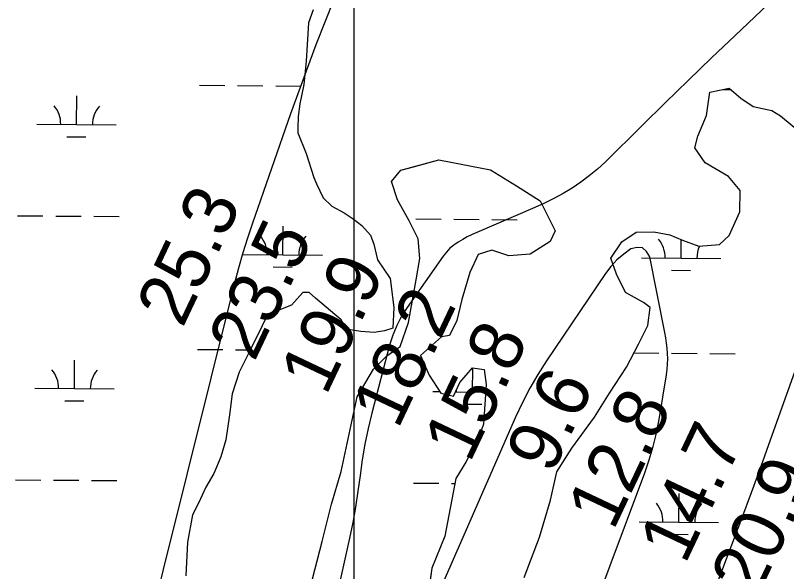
# Model space of a CAD drawing. Extents: x 3271442 to 3309282, y 752266 to 777610.
# Drawn here: x 3285650 to 3286622, y 765409 to 766109 of the extents above; entities that cross this region are included whole.
import ezdxf

# ---------------------------------------------------------------- set-up
doc = ezdxf.new("R2010")
doc.units = 0
for name, color, linetype in [('V-GRID-MAJR', 7, 'Continuous'), ('V-RIVR-RANG', 7, 'Continuous'), ('V-SITE-VEGE', 7, 'Continuous'), ('V-TOPO-DPTH', 7, 'Continuous'), ('V-TOPO-MINR', 7, 'Continuous'), ('V-TOPO-SHOR', 7, 'Continuous'), ('V-WETL-SWMP', 7, 'Continuous')]:
    doc.layers.add(name, color=color, linetype=linetype)

msp = doc.modelspace()

# ---------------------------------------------------------------- linework, layer by layer
at = {"layer": 'V-GRID-MAJR'}
msp.add_spline([(3286078.01, 757644.71), (3286077.13, 763703.55), (3286076.24, 769765.48), (3286075.36, 775827.44), (3286075.36, 775830.49)], degree=3, dxfattribs=at)
at = {"layer": 'V-SITE-VEGE'}
for p, q in [((3286025.27, 766116.4), (3286019.52, 766099.95)), ((3286019.52, 766099.95), (3286016.48, 766051.66)), ((3286016.48, 766051.66), (3286013.52, 766022.12)), ((3286013.52, 766022.12), (3286008.31, 765997.7)), ((3286521.18, 765982.96), (3286525.36, 766012.34)), ((3286525.36, 766012.34), (3286549.63, 766017.37)), ((3286549.63, 766017.37), (3286564.64, 766005.18)), ((3286564.64, 766005.18), (3286580.03, 765994.46)), ((3286008.31, 765997.7), (3286006.54, 765981.8)), ((3286580.03, 765994.46), (3286603.52, 765989.58)), ((3286006.54, 765981.8), (3286005.91, 765967.59)), ((3286510.41, 765956.92), (3286521.18, 765982.96)), ((3286603.52, 765989.58), (3286614.51, 765982.54)), ((3286614.51, 765982.54), (3286643.8, 765958.53)), ((3286005.91, 765967.59), (3286005.89, 765961.34)), ((3286005.89, 765961.34), (3286016.58, 765935.15)), ((3286506.31, 765942.24), (3286510.41, 765956.92)), ((3286519.45, 765923.44), (3286506.31, 765942.24)), ((3286016.58, 765935.15), (3286026.11, 765905)), ((3286135.79, 765914.12), (3286183.62, 765927.14)), ((3286183.62, 765927.14), (3286211.89, 765921.87)), ((3286548.77, 765906.41), (3286519.45, 765923.44)), ((3286123.97, 765899.84), (3286135.79, 765914.12)), ((3286211.89, 765921.87), (3286248.97, 765914.72)), ((3286248.97, 765914.72), (3286281.58, 765894.73)), ((3286026.11, 765905), (3286029.49, 765897.03)), ((3286563.76, 765888.7), (3286548.77, 765906.41)), ((3286029.49, 765897.03), (3286037.94, 765879.37)), ((3286131.58, 765877.03), (3286123.97, 765899.84)), ((3286281.58, 765894.73), (3286311.63, 765875.49)), ((3286563.27, 765861.88), (3286563.76, 765888.7)), ((3286037.94, 765879.37), (3286048.7, 765869.1)), ((3286146.53, 765850.51), (3286131.58, 765877.03)), ((3286311.63, 765875.49), (3286330.2, 765837.93)), ((3286048.7, 765869.1), (3286064.58, 765860.51)), ((3286064.58, 765860.51), (3286075.91, 765853.08)), ((3286549.54, 765831.81), (3286563.27, 765861.88)), ((3286075.91, 765853.08), (3286086.68, 765844.51)), ((3286086.68, 765844.51), (3286097.43, 765832.53)), ((3286157.46, 765827.68), (3286146.53, 765850.51)), ((3286330.2, 765837.93), (3286324.26, 765824.36)), ((3286414.29, 765823.96), (3286432.35, 765836.37)), ((3286432.35, 765836.37), (3286454.76, 765836.64)), ((3286454.76, 765836.64), (3286474.95, 765832.88)), ((3286097.43, 765832.53), (3286101.93, 765821.15)), ((3286159.92, 765803.05), (3286157.46, 765827.68)), ((3286474.95, 765832.88), (3286490.72, 765826.19)), ((3286490.72, 765826.19), (3286511.63, 765818.39)), ((3286537.36, 765820.47), (3286549.54, 765831.81)), ((3286101.93, 765821.15), (3286106.39, 765801.24)), ((3286324.26, 765824.36), (3286298.84, 765808.68)), ((3286400.6, 765803.44), (3286414.29, 765823.96)), ((3286511.63, 765818.39), (3286537.36, 765820.47)), ((3286233.43, 765808.23), (3286222.68, 765785.5)), ((3286250.36, 765813.67), (3286233.43, 765808.23)), ((3286272, 765806.22), (3286250.36, 765813.67)), ((3286298.84, 765808.68), (3286272, 765806.22)), ((3286106.39, 765801.24), (3286122.21, 765777.87)), ((3286155.02, 765776.25), (3286159.92, 765803.05)), ((3286407.49, 765783.2), (3286400.6, 765803.44)), ((3286122.21, 765777.87), (3286127.17, 765741.48)), ((3286145.6, 765722.27), (3286155.02, 765776.25)), ((3286222.68, 765785.5), (3286212.6, 765751.37)), ((3286419.15, 765760.37), (3286407.49, 765783.2)), ((3286012.45, 765760.13), (3285998.18, 765744.28)), ((3286020.41, 765760.1), (3286012.45, 765760.13)), ((3286028.34, 765753.25), (3286020.41, 765760.1)), ((3286441.87, 765747.41), (3286419.15, 765760.37)), ((3286060.62, 765725.84), (3286028.34, 765753.25)), ((3286212.6, 765751.37), (3286206.24, 765724.94)), ((3286450.29, 765741.13), (3286441.87, 765747.41)), ((3285983.95, 765738.66), (3285967.44, 765731.33)), ((3285998.18, 765744.28), (3285983.95, 765738.66)), ((3286127.17, 765741.48), (3286125.93, 765715.34)), ((3286447.25, 765718.73), (3286450.29, 765741.13)), ((3285967.44, 765731.33), (3285961.14, 765718.29)), ((3285961.14, 765718.29), (3285946.24, 765688.23)), ((3286066.82, 765713.88), (3286060.62, 765725.84)), ((3286134.81, 765692.19), (3286145.6, 765722.27)), ((3286206.24, 765724.94), (3286197.33, 765705.87)), ((3286435.39, 765695.26), (3286447.25, 765718.73)), ((3286085.56, 765710.96), (3286066.82, 765713.88)), ((3286102.04, 765709.76), (3286085.56, 765710.96)), ((3286115.12, 765711.98), (3286102.04, 765709.76)), ((3286125.93, 765715.34), (3286115.12, 765711.98)), ((3286187.04, 765704.45), (3286160.48, 765680.68)), ((3286197.33, 765705.87), (3286187.04, 765704.45)), ((3286118.22, 765680.5), (3286134.81, 765692.19)), ((3286420.2, 765666.3), (3286435.39, 765695.26)), ((3285946.24, 765688.23), (3285931.91, 765659.88)), ((3286101.24, 765663.68), (3286118.22, 765680.5)), ((3286160.48, 765680.68), (3286171.39, 765656.02)), ((3285931.91, 765659.88), (3285923.28, 765632.63)), ((3286080.88, 765628.86), (3286101.24, 765663.68)), ((3286210.3, 765647.02), (3286226.18, 765665.33)), ((3286226.18, 765665.33), (3286240.87, 765663.06)), ((3286240.87, 765663.06), (3286243.36, 765644.31)), ((3286398.74, 765633.33), (3286420.2, 765666.3)), ((3286171.39, 765656.02), (3286186.36, 765633.53)), ((3286202.14, 765629.79), (3286210.3, 765647.02)), ((3286243.36, 765644.31), (3286240.2, 765594.35)), ((3285923.28, 765632.63), (3285919.76, 765605.93)), ((3286186.36, 765633.53), (3286202.14, 765629.79)), ((3286379.87, 765603.28), (3286398.74, 765633.33)), ((3286060.62, 765534.52), (3286080.88, 765628.86)), ((3285919.76, 765605.93), (3285915.09, 765574.7)), ((3286351.4, 765564.09), (3286379.87, 765603.28)), ((3286240.2, 765594.35), (3286233.13, 765575.27)), ((3285915.09, 765574.7), (3285908.75, 765553.13)), ((3286233.13, 765575.27), (3286217.57, 765546.68)), ((3286332.53, 765534.41), (3286351.4, 765564.09)), ((3285908.75, 765553.13), (3285900.14, 765532.14)), ((3286217.57, 765546.68), (3286205.35, 765525.79)), ((3286048.31, 765493.78), (3286060.62, 765534.52)), ((3286324.65, 765498.8), (3286332.53, 765534.41)), ((3285900.14, 765532.14), (3285889.84, 765515.13)), ((3286205.35, 765525.79), (3286191.43, 765453.1)), ((3285889.84, 765515.13), (3285880.66, 765494.7)), ((3285880.66, 765494.7), (3285873.21, 765479.96)), ((3286310.48, 765452.2), (3286324.65, 765498.8)), ((3286036.71, 765446.43), (3286048.31, 765493.78)), ((3285873.21, 765479.96), (3285866.82, 765445.89)), ((3285866.82, 765445.89), (3285864.95, 765403.27)), ((3286021.01, 765386.61), (3286036.71, 765446.43)), ((3286191.43, 765453.1), (3286174.72, 765413.12)), ((3286291.15, 765401.21), (3286310.48, 765452.2)), ((3286174.72, 765413.12), (3286169.03, 765372.36))]:
    msp.add_line(p, q, dxfattribs=at)
at = {"layer": 'V-TOPO-DPTH'}
msp.add_lwpolyline([(3286141.36, 764725.96), (3286443.39, 765533.11), (3286449.01, 765549.59), (3286453.99, 765566.24), (3286457.98, 765583.16), (3286461.33, 765600.25), (3286470.68, 765656.69), (3286471.54, 765663.31), (3286472.1, 765669.94), (3286472.21, 765676.6), (3286472, 765683.27), (3286471.44, 765689.93), (3286470.71, 765696.57), (3286469.71, 765703.18), (3286468.54, 765709.77), (3286449.71, 765805.02), (3286445.65, 765811.95), (3286440.52, 765816.38), (3286433.77, 765817.06), (3286425.95, 765815.23), (3286416.78, 765808.6), (3286408.27, 765801.31), (3286400.72, 765793.02), (3286393.81, 765784.06), (3286319.52, 765674.17), (3286308.62, 765657.07), (3286298.37, 765639.61), (3286289.09, 765621.61), (3286280.46, 765603.26), (3286092.7, 765174.28)], dxfattribs=at)
at = {"layer": 'V-TOPO-MINR'}
for points in [[(3286062.67, 766158.12), (3286028.87, 766072), (3285996.92, 765985.12), (3285948.83, 765847.51), (3285942.58, 765828.78), (3285936.67, 765809.95), (3285931.28, 765790.97), (3285926.23, 765771.88), (3285836.27, 765411.46), (3285825.32, 765365.74), (3285814.97, 765319.89), (3285805.49, 765273.85), (3285796.61, 765227.69), (3285789.16, 765181.32), (3285783.03, 765134.8), (3285778.87, 765088.07), (3285776.04, 765041.19), (3285769.47, 764873.26), (3285713.83, 764763.83), (3285687.23, 764708.6), (3285683.59, 764700.44)], [(3286598.28, 766122.93), (3286557.12, 766083.91), (3286527.66, 766055.81), (3286498.31, 766027.6), (3286469.13, 765999.2), (3286440.06, 765970.7), (3286393.29, 765924.55), (3286383.55, 765915.56), (3286373.45, 765907.02), (3286362.8, 765899.17), (3286351.8, 765891.78), (3286340.37, 765885.01), (3286328.76, 765878.6), (3286316.87, 765872.73), (3286304.79, 765867.22), (3286231.63, 765835.87), (3286225.59, 765833.13), (3286219.64, 765830.22), (3286213.81, 765827.07), (3286208.07, 765823.75), (3286202.68, 765820), (3286197.66, 765815.85), (3286193.18, 765811.12), (3286189.08, 765805.99), (3286143.74, 765741.43), (3286136.74, 765730.23), (3286130.59, 765718.64), (3286125.7, 765706.45), (3286121.65, 765693.88), (3286099.13, 765608.38), (3286094.44, 765588.9), (3286090.33, 765569.31), (3286087.07, 765549.56), (3286084.37, 765529.7), (3286081.79, 765509.81), (3286078.79, 765490), (3286075.16, 765470.29), (3286071.1, 765450.66), (3286038.19, 765303.19)], [(3286141.36, 764725.96), (3286443.39, 765533.11), (3286449.01, 765549.59), (3286453.99, 765566.24), (3286457.98, 765583.16), (3286461.33, 765600.25), (3286470.68, 765656.69), (3286471.54, 765663.31), (3286472.1, 765669.94), (3286472.21, 765676.6), (3286472, 765683.27), (3286471.44, 765689.93), (3286470.71, 765696.57), (3286469.71, 765703.18), (3286468.54, 765709.77), (3286449.71, 765805.02), (3286445.65, 765811.95), (3286440.52, 765816.38), (3286433.77, 765817.06), (3286425.95, 765815.23), (3286416.78, 765808.6), (3286408.27, 765801.31), (3286400.72, 765793.02), (3286393.81, 765784.06), (3286319.52, 765674.17), (3286308.62, 765657.07), (3286298.37, 765639.61), (3286289.09, 765621.61), (3286280.46, 765603.26), (3286092.7, 765174.28)], [(3286182.77, 764319.84), (3286261.5, 764619.04), (3286268.87, 764645.82), (3286276.62, 764672.49), (3286284.96, 764698.97), (3286293.69, 764725.34), (3286347.74, 764882.72), (3286384.31, 764987.5), (3286421.57, 765092.03), (3286459.89, 765196.18), (3286498.9, 765300.08), (3286553.15, 765442.39), (3286565.59, 765475.32), (3286577.88, 765508.29), (3286589.97, 765541.34), (3286601.93, 765574.44), (3286684.27, 765804.68)]]:
    msp.add_lwpolyline(points, dxfattribs=at)
at = {"layer": 'V-TOPO-SHOR'}
for points in [[(3286025.27, 766116.41), (3286019.52, 766099.95), (3286016.48, 766051.66), (3286013.52, 766022.12), (3286008.31, 765997.7), (3286006.54, 765981.8), (3286005.91, 765967.59), (3286005.89, 765961.34), (3286016.58, 765935.15), (3286026.11, 765905), (3286029.49, 765897.03), (3286037.94, 765879.37), (3286048.7, 765869.1), (3286064.58, 765860.51), (3286075.91, 765853.08), (3286086.68, 765844.51), (3286097.43, 765832.53), (3286101.93, 765821.15), (3286106.39, 765801.24), (3286122.21, 765777.87), (3286127.17, 765741.48), (3286125.93, 765715.34), (3286115.12, 765711.98), (3286102.04, 765709.76), (3286085.56, 765710.96), (3286066.82, 765713.88), (3286060.62, 765725.84), (3286028.34, 765753.25), (3286020.41, 765760.1), (3286012.45, 765760.13), (3285998.18, 765744.28), (3285983.95, 765738.66), (3285967.44, 765731.33), (3285961.14, 765718.29), (3285946.24, 765688.23), (3285931.91, 765659.88), (3285923.28, 765632.63), (3285919.76, 765605.93), (3285915.09, 765574.7), (3285908.75, 765553.13), (3285900.14, 765532.14), (3285889.84, 765515.13), (3285880.66, 765494.71), (3285873.21, 765479.96), (3285866.82, 765445.89), (3285864.95, 765403.27)], [(3286435.39, 765695.26), (3286447.25, 765718.73), (3286450.29, 765741.13), (3286441.87, 765747.41), (3286419.15, 765760.37), (3286407.49, 765783.2), (3286400.6, 765803.44), (3286414.29, 765823.96), (3286432.35, 765836.37), (3286454.76, 765836.64), (3286474.95, 765832.88), (3286490.72, 765826.19), (3286511.63, 765818.39), (3286537.36, 765820.47), (3286549.54, 765831.81), (3286563.27, 765861.88), (3286563.76, 765888.7), (3286548.77, 765906.41), (3286519.45, 765923.44), (3286506.31, 765942.24), (3286510.41, 765956.92), (3286521.18, 765982.96), (3286525.36, 766012.34), (3286549.63, 766017.37), (3286564.64, 766005.18), (3286580.03, 765994.46), (3286603.52, 765989.58), (3286614.51, 765982.54), (3286643.8, 765958.53)], [(3286021.01, 765386.61), (3286036.71, 765446.43), (3286048.31, 765493.78), (3286060.62, 765534.52), (3286080.88, 765628.86), (3286101.24, 765663.68), (3286118.22, 765680.5), (3286134.81, 765692.19), (3286145.6, 765722.27), (3286150.12, 765747.97), (3286155.02, 765776.25), (3286159.92, 765803.05), (3286157.46, 765827.68), (3286146.53, 765850.51), (3286131.59, 765877.03), (3286123.97, 765899.84), (3286135.79, 765914.12), (3286151.61, 765918.46), (3286183.62, 765927.14), (3286211.89, 765921.87), (3286248.97, 765914.72), (3286281.58, 765894.73), (3286311.63, 765875.49), (3286330.2, 765837.93), (3286324.26, 765824.36), (3286298.84, 765808.68), (3286272, 765806.22), (3286250.36, 765813.67), (3286233.43, 765808.23), (3286222.68, 765785.5), (3286212.6, 765751.37), (3286206.24, 765724.94), (3286197.33, 765705.87), (3286187.04, 765704.45), (3286160.48, 765680.68), (3286171.39, 765656.02), (3286186.36, 765633.53), (3286202.14, 765629.79), (3286210.3, 765647.02), (3286226.18, 765665.33), (3286240.87, 765663.06), (3286243.36, 765644.31), (3286240.2, 765594.35), (3286233.13, 765575.27), (3286217.57, 765546.68), (3286205.35, 765525.79), (3286191.43, 765453.1), (3286174.72, 765413.12), (3286169.03, 765372.36)], [(3286291.15, 765401.21), (3286310.48, 765452.2), (3286324.65, 765498.8), (3286332.53, 765534.41), (3286351.4, 765564.09), (3286379.87, 765603.28), (3286398.74, 765633.33), (3286420.2, 765666.3), (3286435.39, 765695.26)]]:
    msp.add_lwpolyline(points, dxfattribs=at)
at = {"layer": 'V-WETL-SWMP'}
for p, q in [((3286025.27, 766116.41), (3286019.52, 766099.95)), ((3286019.52, 766099.95), (3286016.48, 766051.66)), ((3286016.48, 766051.66), (3286013.52, 766022.12)), ((3285882.05, 766021.22), (3285914.05, 766020.96)), ((3285930.05, 766020.83), (3285962.05, 766020.56)), ((3285978.05, 766020.43), (3286010.05, 766020.17)), ((3286013.52, 766022.12), (3286008.31, 765997.7)), ((3286521.18, 765982.96), (3286525.36, 766012.34)), ((3286525.36, 766012.34), (3286549.63, 766017.37)), ((3286541.99, 766015.79), (3286551.68, 766015.71)), ((3286549.63, 766017.37), (3286564.64, 766005.18)), ((3285727.05, 765971.76), (3285727.34, 766007.76)), ((3286564.64, 766005.18), (3286580.03, 765994.46)), ((3286008.31, 765997.7), (3286006.54, 765981.8)), ((3286580.03, 765994.46), (3286603.52, 765989.57)), ((3286006.54, 765981.8), (3286005.91, 765967.59)), ((3286510.41, 765956.92), (3286521.18, 765982.96)), ((3286603.52, 765989.57), (3286614.51, 765982.54)), ((3286614.51, 765982.54), (3286643.8, 765958.53)), ((3285677.05, 765972.17), (3285777.05, 765971.35)), ((3286005.91, 765967.59), (3286005.89, 765961.34)), ((3286005.89, 765961.34), (3286016.58, 765935.15)), ((3285714.92, 765956.43), (3285738.92, 765956.23)), ((3286506.31, 765942.24), (3286510.41, 765956.92)), ((3286519.45, 765923.44), (3286506.31, 765942.24)), ((3286016.58, 765935.15), (3286026.11, 765905)), ((3286135.79, 765914.12), (3286183.62, 765927.14)), ((3286183.62, 765927.14), (3286211.89, 765921.87)), ((3286548.77, 765906.41), (3286519.45, 765923.44)), ((3286123.97, 765899.84), (3286135.79, 765914.12)), ((3286211.89, 765921.87), (3286248.97, 765914.72)), ((3286248.97, 765914.72), (3286281.58, 765894.73)), ((3286026.11, 765905), (3286029.49, 765897.03)), ((3286563.76, 765888.7), (3286548.77, 765906.41)), ((3286029.49, 765897.03), (3286037.94, 765879.37)), ((3286131.59, 765877.03), (3286123.97, 765899.84)), ((3286281.58, 765894.73), (3286311.63, 765875.49)), ((3286563.27, 765861.88), (3286563.76, 765888.7)), ((3286037.94, 765879.37), (3286048.7, 765869.1)), ((3286146.53, 765850.51), (3286131.59, 765877.03)), ((3286311.63, 765875.49), (3286330.2, 765837.93)), ((3286048.7, 765869.1), (3286064.58, 765860.51)), ((3285652.69, 765856.93), (3285684.69, 765856.67)), ((3285700.69, 765856.54), (3285732.69, 765856.27)), ((3285748.69, 765856.14), (3285780.69, 765855.88)), ((3286064.58, 765860.51), (3286075.91, 765853.08)), ((3286549.54, 765831.81), (3286563.27, 765861.88)), ((3286075.91, 765853.08), (3286086.68, 765844.51)), ((3286086.68, 765844.51), (3286097.43, 765832.53)), ((3286157.46, 765827.68), (3286146.53, 765850.51)), ((3286154.58, 765852.8), (3286186.58, 765852.54)), ((3286202.58, 765852.4), (3286234.58, 765852.14)), ((3286250.58, 765852.01), (3286282.58, 765851.75)), ((3285987.14, 765807.75), (3285987.44, 765843.75)), ((3286330.2, 765837.93), (3286324.26, 765824.36)), ((3286414.28, 765823.96), (3286432.35, 765836.37)), ((3286432.35, 765836.37), (3286454.76, 765836.64)), ((3286454.76, 765836.64), (3286474.95, 765832.88)), ((3286097.43, 765832.53), (3286101.93, 765821.15)), ((3286159.92, 765803.05), (3286157.46, 765827.68)), ((3286474.95, 765832.88), (3286490.72, 765826.19)), ((3286489.03, 765803.61), (3286489.22, 765826.83)), ((3286490.72, 765826.19), (3286511.63, 765818.38)), ((3286537.36, 765820.47), (3286549.54, 765831.81)), ((3286101.93, 765821.15), (3286106.39, 765801.24)), ((3286324.26, 765824.36), (3286298.84, 765808.68)), ((3286400.6, 765803.45), (3286414.28, 765823.96)), ((3286511.63, 765818.38), (3286537.36, 765820.47)), ((3285937.14, 765808.16), (3286037.14, 765807.34)), ((3286233.43, 765808.23), (3286222.67, 765785.5)), ((3286250.36, 765813.67), (3286233.43, 765808.23)), ((3286272, 765806.22), (3286250.36, 765813.67)), ((3286298.84, 765808.68), (3286272, 765806.22)), ((3286106.39, 765801.24), (3286122.21, 765777.87)), ((3286155.02, 765776.25), (3286159.92, 765803.05)), ((3286407.49, 765783.21), (3286400.6, 765803.45)), ((3286439.03, 765804.02), (3286539.03, 765803.2)), ((3285975.01, 765792.42), (3285999.01, 765792.22)), ((3286476.9, 765788.28), (3286500.9, 765788.08)), ((3286122.21, 765777.87), (3286127.17, 765741.48)), ((3286145.6, 765722.27), (3286155.02, 765776.25)), ((3286222.67, 765785.5), (3286212.6, 765751.37)), ((3286419.15, 765760.37), (3286407.49, 765783.21)), ((3286012.45, 765760.14), (3285998.18, 765744.28)), ((3286020.41, 765760.1), (3286012.45, 765760.14)), ((3286028.34, 765753.25), (3286020.41, 765760.1)), ((3286441.87, 765747.41), (3286419.15, 765760.37)), ((3286060.62, 765725.84), (3286028.34, 765753.25)), ((3286212.6, 765751.37), (3286206.24, 765724.94)), ((3286450.29, 765741.13), (3286441.87, 765747.41)), ((3285983.95, 765738.66), (3285967.44, 765731.33)), ((3285998.18, 765744.28), (3285983.95, 765738.66)), ((3286127.17, 765741.48), (3286125.93, 765715.34)), ((3286447.25, 765718.73), (3286450.29, 765741.13)), ((3285967.44, 765731.33), (3285961.14, 765718.29)), ((3285961.14, 765718.29), (3285946.24, 765688.23)), ((3286066.82, 765713.88), (3286060.62, 765725.84)), ((3286134.81, 765692.19), (3286145.6, 765722.27)), ((3286206.24, 765724.94), (3286197.33, 765705.87)), ((3286435.39, 765695.26), (3286447.25, 765718.73)), ((3286085.56, 765710.96), (3286066.82, 765713.88)), ((3286102.04, 765709.76), (3286085.56, 765710.96)), ((3286115.12, 765711.98), (3286102.04, 765709.76)), ((3286125.93, 765715.34), (3286115.12, 765711.98)), ((3286187.04, 765704.45), (3286160.48, 765680.68)), ((3286197.33, 765705.87), (3286187.04, 765704.45)), ((3286118.22, 765680.51), (3286134.81, 765692.19)), ((3286420.2, 765666.3), (3286435.39, 765695.26)), ((3285879.31, 765688.56), (3285911.31, 765688.3)), ((3285927.31, 765688.16), (3285946.12, 765688.01)), ((3285946.24, 765688.23), (3285931.91, 765659.87)), ((3286101.24, 765663.68), (3286118.22, 765680.51)), ((3286160.48, 765680.68), (3286171.39, 765656.02)), ((3286429.5, 765684.03), (3286461.2, 765683.77)), ((3286477.2, 765683.64), (3286509.2, 765683.37)), ((3286525.2, 765683.24), (3286557.2, 765682.98)), ((3285724.31, 765639.09), (3285724.6, 765675.09)), ((3285931.91, 765659.87), (3285923.28, 765632.63)), ((3286080.88, 765628.86), (3286101.24, 765663.68)), ((3286210.3, 765647.02), (3286226.18, 765665.33)), ((3286226.18, 765665.33), (3286240.87, 765663.06)), ((3286226.2, 765634.96), (3286226.45, 765665.29)), ((3286240.87, 765663.06), (3286243.36, 765644.31)), ((3286398.74, 765633.33), (3286420.2, 765666.3)), ((3286171.39, 765656.02), (3286186.36, 765633.54)), ((3286202.14, 765629.79), (3286210.3, 765647.02)), ((3286243.36, 765644.31), (3286240.2, 765594.35)), ((3285674.31, 765639.51), (3285774.31, 765638.68)), ((3285923.28, 765632.63), (3285919.76, 765605.94)), ((3286176.2, 765635.37), (3286185.18, 765635.3)), ((3286186.36, 765633.54), (3286202.14, 765629.79)), ((3286204.67, 765635.14), (3286242.76, 765634.82)), ((3286379.87, 765603.28), (3286398.74, 765633.33)), ((3285712.18, 765623.76), (3285736.18, 765623.56)), ((3286060.62, 765534.52), (3286080.88, 765628.86)), ((3286214.07, 765619.63), (3286238.07, 765619.43)), ((3285919.76, 765605.94), (3285915.09, 765574.7)), ((3286351.4, 765564.09), (3286379.87, 765603.28)), ((3286240.2, 765594.35), (3286233.13, 765575.27)), ((3285915.09, 765574.7), (3285908.75, 765553.13)), ((3286233.13, 765575.27), (3286217.57, 765546.68)), ((3286332.53, 765534.41), (3286351.4, 765564.09)), ((3285908.75, 765553.13), (3285900.14, 765532.14)), ((3286217.57, 765546.68), (3286205.35, 765525.79)), ((3286048.31, 765493.78), (3286060.62, 765534.52)), ((3286324.65, 765498.8), (3286332.53, 765534.41)), ((3285649.95, 765524.27), (3285681.95, 765524.01)), ((3285697.95, 765523.87), (3285729.95, 765523.61)), ((3285745.95, 765523.48), (3285777.95, 765523.22)), ((3285900.14, 765532.14), (3285889.84, 765515.13)), ((3286205.35, 765525.79), (3286191.43, 765453.1)), ((3285889.84, 765515.13), (3285880.66, 765494.71)), ((3286151.84, 765520.14), (3286183.84, 765519.87)), ((3286199.84, 765519.74), (3286204.19, 765519.7)), ((3286486.29, 765470.95), (3286486.59, 765506.95)), ((3285880.66, 765494.71), (3285873.21, 765479.96)), ((3286310.48, 765452.2), (3286324.65, 765498.8)), ((3286036.71, 765446.44), (3286048.31, 765493.78)), ((3285873.21, 765479.96), (3285866.82, 765445.89)), ((3286436.29, 765471.36), (3286536.29, 765470.54)), ((3286474.16, 765455.62), (3286498.16, 765455.42)), ((3285866.82, 765445.89), (3285864.94, 765403.28)), ((3286021.01, 765386.61), (3286036.71, 765446.44)), ((3286191.43, 765453.1), (3286174.72, 765413.12)), ((3286291.15, 765401.21), (3286310.48, 765452.2)), ((3286174.72, 765413.12), (3286169.03, 765372.36))]:
    msp.add_line(p, q, dxfattribs=at)
for centre, start, end in [((3285671.81, 765972.69), 358.75626, 40.29991), ((3285782.29, 765971.78), 138.75625, 180.29991), ((3285931.9, 765808.68), 358.75626, 40.29991), ((3286042.39, 765807.77), 138.75625, 180.29991), ((3286433.79, 765804.54), 358.75626, 40.29991), ((3286544.28, 765803.63), 155.16176, 180.29991), ((3285669.07, 765640.02), 358.75626, 40.29991), ((3285779.55, 765639.11), 138.75625, 180.29991), ((3286170.96, 765635.89), 358.75626, 3.78929), ((3286431.05, 765471.88), 358.75626, 40.29991), ((3286541.54, 765470.97), 138.75625, 180.29991)]:
    msp.add_arc(centre, 35.25, start, end, dxfattribs=at)

# ---------------------------------------------------------------- texts
at = {"layer": 'V-RIVR-RANG'}
for s, p in [('25.3', (3285860.57, 765714.33)), ('23.5', (3285951.06, 765671.78)), ('19.9', (3286041.45, 765628.99)), ('18.2', (3286132.06, 765586.68)), ('15.8', (3286222.55, 765544.13)), ('9.6', (3286326.48, 765529.95)), ('12.8', (3286403.55, 765459.03)), ('14.7', (3286494.04, 765416.48)), ('20.9', (3286584.43, 765373.69)), ('23.9', (3286674.92, 765331.15))]:
    msp.add_text(s, height=67, rotation=64.67833, dxfattribs=at).set_placement(p)

doc.saveas('drawing.dxf')
